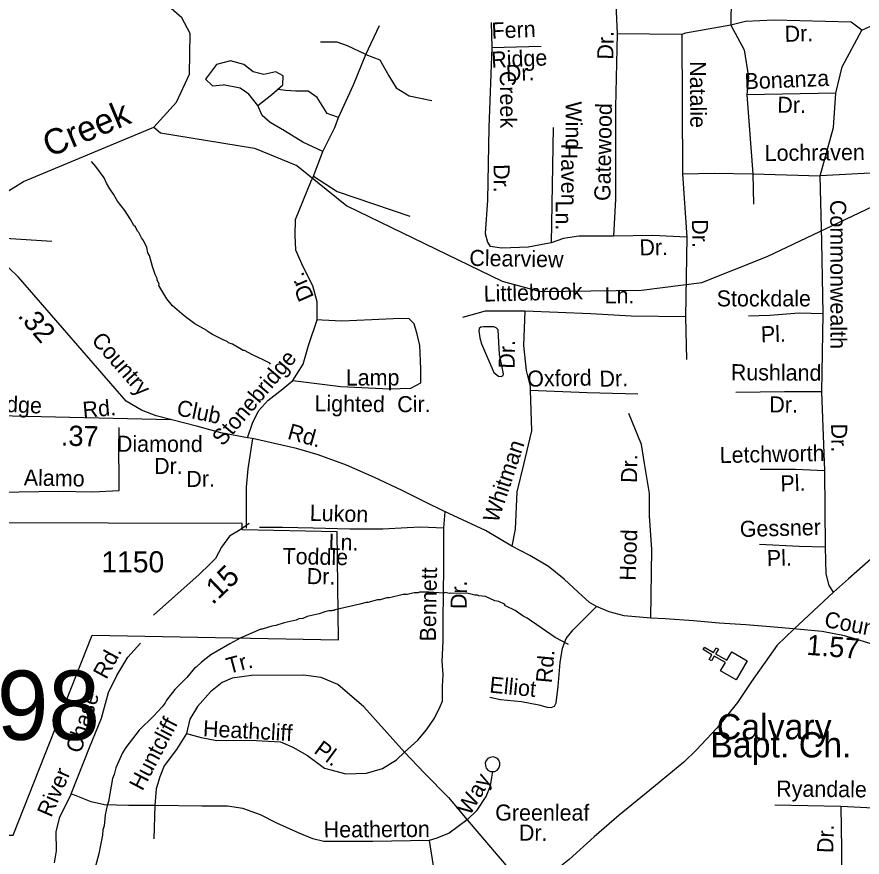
# Model space of a CAD drawing. Extents: x 1547597 to 1699558, y 810033 to 920809.
# Drawn here: x 1597107 to 1602112, y 851025 to 855999 of the extents above; entities that cross this region are included whole.
import ezdxf

# ---------------------------------------------------------------- set-up
doc = ezdxf.new("R2010")
doc.units = 0
for name, color, linetype in [('Exist Boundary Political City Limit New', 7, 'Continuous'), ('Exist Cultural Church CELL', 7, 'Continuous'), ('Exist Cultural Church Label', 7, 'Continuous'), ('Exist Hydrographic Creek Single Shore', 7, 'Continuous'), ('Exist Hydrographic Misc Water Feature', 7, 'Continuous'), ('Exist Road Non-System Type 51', 7, 'Continuous'), ('Exist Road Non-System Type 51 Label', 7, 'Continuous'), ('Exist Road Secondary Mileage Hundredths English Label', 7, 'Continuous'), ('Exist Road Secondary Structure Standard Bridge CELL', 7, 'Continuous'), ('Exist Road Secondary Structure Standard Bridge Number Label', 7, 'Continuous'), ('Exist Road Secondary Type 51 Attributed', 7, 'Continuous'), ('Exist Road Secondary Type 51 Label', 7, 'Continuous'), ('Exist Road Secondary Type 51 Number Label', 7, 'Continuous'), ('Map Preparation Boundary City Limit Buffer Line', 7, 'Continuous'), ('Old_Level_32', 7, 'Continuous')]:
    doc.layers.add(name, color=color, linetype=linetype)

msp = doc.modelspace()

# ---------------------------------------------------------------- linework, layer by layer
at = {"layer": 'Exist Boundary Political City Limit New'}
msp.add_lwpolyline([(1598966.2, 848889), (1598696.7, 848933.6), (1598735.8, 849260.4), (1597051.5, 849266), (1596744.3, 849248.9), (1596741.6, 849203.1), (1596587.6, 849194.5), (1596790.6, 850274.8), (1596971.2, 851155.7), (1597083.9, 851155.7), (1597552.8, 852338.7), (1599010.8, 852311.7), (1599004, 852951.6), (1598440.1, 852963.6), (1598441.2, 853000.9), (1596057.5, 853006.4)], dxfattribs=at)
at = {"layer": 'Exist Cultural Church CELL'}
msp.add_lwpolyline([(1601273.5, 852127.9), (1601302.2, 852177), (1601236.5, 852215.5), (1601220.4, 852187.9), (1601206.6, 852196), (1601222.8, 852223.6), (1601170.9, 852254), (1601179, 852267.9), (1601230.9, 852237.4), (1601247, 852265), (1601260.8, 852257), (1601244.6, 852229.4), (1601310.3, 852190.9), (1601339.6, 852240.5), (1601431.4, 852186.7), (1601365.4, 852074)], close=True, dxfattribs=at)
at = {"layer": 'Exist Hydrographic Creek Single Shore'}
for points in [[(1597916.6, 855346.8), (1598051.6, 855495), (1598128.7, 855660.9), (1598132.7, 855900.5), (1598083.7, 855993.4), (1597959.6, 856104.2), (1597769.6, 856200), (1597613.6, 856400.1), (1597549.6, 856634.5), (1597500.6, 856710.9), (1597454.7, 856961.4), (1597490.7, 857151.1), (1597755.1, 857446.8), (1598364.4, 858096.9), (1598493.9, 858519.8), (1598638.6, 858913.6)], [(1596005.6, 853287.9), (1596117.6, 853594.1), (1596743.8, 854808.1), (1596918.7, 854884.4), (1597145.7, 855024.3), (1597916.6, 855346.8)]]:
    msp.add_lwpolyline(points, dxfattribs=at)
at = {"layer": 'Exist Hydrographic Misc Water Feature'}
for points in [[(1597916.6, 855346.8), (1597957.7, 855313.1), (1598514.6, 855223), (1598763.6, 855119.5), (1599060.6, 854880.4), (1599980.6, 854435), (1600204.6, 854374.6), (1600804.6, 854382.2), (1601163.6, 854427.4), (1601549.7, 854580.4), (1602405.6, 854986.5), (1603296.7, 855565.9), (1603514.7, 855656.7), (1603614.6, 855661.2)], [(1598609.3, 853943), (1598605.4, 853949), (1598565.7, 853969.5), (1598502.2, 853998.5), (1598454.6, 854025.1), (1598446.6, 854025.2), (1598383.1, 854062.1), (1598359.3, 854070.4), (1598351.4, 854078.5), (1598327.5, 854086.9), (1598264, 854119.7), (1598240.1, 854134.1), (1598232.3, 854142.2), (1598160.9, 854183.2), (1598097.6, 854230.1), (1598028.4, 854289), (1597995, 854329.5), (1597948.1, 854410.1), (1597948.2, 854418.1), (1597936.5, 854442.2), (1597936.6, 854450.2), (1597925, 854474.4), (1597909.7, 854522.6), (1597892.6, 854586.9), (1597882.8, 854602.9), (1597875.2, 854635), (1597855.7, 854675.3), (1597844, 854691.5), (1597828.5, 854723.7), (1597820.6, 854731.8), (1597808.9, 854756), (1597799.1, 854764.1), (1597777.6, 854804.4), (1597746.3, 854852.8), (1597703.1, 854909.4), (1597679.6, 854949.7), (1597656, 854982), (1597636.5, 855014.3), (1597623, 855046.5), (1597573.9, 855113.2), (1597547.8, 855142.6)], [(1599847.2, 854098.7), (1599857.4, 854064.7), (1599930.7, 853893.6), (1599959.1, 853871.7), (1599974.8, 853869.7), (1599985.9, 853876.6), (1599988.9, 853887.1), (1599965.1, 854001.7), (1599956.2, 854147), (1599945.2, 854159.4), (1599931.9, 854164.8), (1599869, 854165.5), (1599854.3, 854161.6), (1599845, 854154.7), (1599841.3, 854141.3), (1599847.2, 854098.7)], [(1600373.7, 852284.7), (1600294.3, 852325.8), (1600127.9, 852440.1), (1600104.1, 852452.4), (1600056.7, 852485.1), (1600001, 852513.8), (1599993.2, 852522), (1599961.4, 852538.4), (1599937.4, 852542.7), (1599881.9, 852567.5), (1599842, 852572.1), (1599834, 852576.2), (1599818, 852576.4), (1599778.1, 852584.9), (1599674.3, 852588.4), (1599666.3, 852586.5), (1599642.3, 852590.8), (1599634.3, 852586.9), (1599546.4, 852594.2), (1599490.4, 852593), (1599482.3, 852589.1), (1599458.4, 852589.4), (1599418.2, 852580), (1599394.3, 852580.3), (1599314.1, 852559.5), (1599298.1, 852559.7), (1599257.9, 852548.2), (1599242, 852548.4), (1599185.8, 852533.2), (1599175.8, 852533.4), (1599137.6, 852521.9), (1598991.3, 852489.9), (1598985.3, 852486), (1598975.2, 852486.1), (1598969.2, 852482.3), (1598953.2, 852482.5), (1598929.2, 852476.8), (1598897, 852465.3), (1598824.8, 852450.3), (1598800.7, 852438.6), (1598776.6, 852434.9), (1598760.5, 852427.2), (1598688.4, 852412.2), (1598640.2, 852396.8), (1598616.2, 852393.2), (1598560, 852374), (1598552, 852374.1), (1598433.4, 852323.7), (1598366.9, 852288.7), (1598256, 852222.2), (1598199.5, 852179.1), (1598169.1, 852149.5), (1598159, 852143.6), (1598112.3, 852088.3), (1598041.4, 852017.3), (1597992.5, 851954), (1597984.3, 851938.1), (1597966.1, 851914.4), (1597915.3, 851859.1), (1597830.2, 851776.3), (1597750.9, 851673.4), (1597732.4, 851641.7), (1597693.2, 851554.2), (1597682.7, 851514.4), (1597672.4, 851490.6), (1597648.5, 851354.9), (1597640.2, 851331), (1597629.5, 851275.2), (1597622.6, 851211.3), (1597616.2, 851187.4), (1597613.9, 851155.5), (1597596.8, 851075.7), (1597594.4, 851051.8), (1597569.3, 850964.1)]]:
    msp.add_lwpolyline(points, dxfattribs=at)
at = {"layer": 'Exist Road Non-System Type 51'}
msp.add_line((1599635.2, 852975.4), (1599641.8, 853069.4), dxfattribs=at)
for points in [[(1601338.2, 856272.2), (1601333.9, 855950.3)], [(1600647.8, 856208.1), (1600660.9, 855899.3)], [(1602110.2, 855920.2), (1602046.7, 855967.7), (1601590.3, 855980.8), (1601420.8, 855972.1), (1601333.9, 855950.3)], [(1599172.4, 855776.7), (1599253, 855948.7)], [(1599914.8, 855966.3), (1599919.1, 855818.4)], [(1601333.9, 855950.3), (1601065.1, 855903.6), (1601043.4, 855894.9)], [(1601333.9, 855950.3), (1601412.9, 855803.6), (1601438.9, 855642.6), (1601429.5, 855537.1)], [(1601956.2, 855547), (1601993.9, 855704.5), (1602110.2, 855920.2), (1602161.5, 855944.2), (1602243.6, 855944.2), (1602298.3, 855886), (1602339.4, 855776.4), (1602336, 855666.8), (1602329.1, 855601.8), (1602342.8, 855512.8), (1602376.9, 855469.4)], [(1600660.9, 855899.3), (1600652.2, 855464.2), (1600652.2, 854920.5), (1600639.3, 854700.6)], [(1601043.4, 855894.9), (1600660.9, 855899.3)], [(1601043.4, 855894.9), (1601047.4, 855070.1)], [(1599172.4, 855776.7), (1599065, 855827.7), (1599003.2, 855849.3), (1598903.8, 855849.3)], [(1599919.1, 855818.4), (1600210.3, 855827.1)], [(1599011.3, 855403), (1599099.9, 855596.6), (1599172.4, 855776.7)], [(1599172.4, 855776.7), (1599255.7, 855744.4), (1599309.4, 855650.3), (1599352.4, 855580.4), (1599430.3, 855532.1), (1599564.6, 855505.2)], [(1599919.1, 855818.4), (1599901.7, 855344.2), (1599893, 854913.6), (1599880, 854717.8), (1599893, 854665.6), (1599909, 854639.7)], [(1598533.2, 855475.6), (1598616.4, 855540.1), (1598680.9, 855596.6), (1598683.6, 855650.3), (1598640.6, 855674.5), (1598568.1, 855658.4), (1598506.3, 855674.5), (1598449.9, 855717.5), (1598372, 855739), (1598288.7, 855717.5), (1598224.3, 855631.5), (1598264.6, 855591.2), (1598329, 855596.6)], [(1598533.2, 855475.6), (1598479.4, 855542.8), (1598428.4, 855577.8), (1598329, 855596.6)], [(1599011.3, 855403), (1598944.1, 855427.2), (1598885, 855521.3), (1598831.3, 855558.9), (1598758.8, 855558.9), (1598699.7, 855564.3), (1598651.3, 855569.7)], [(1601956.2, 855547), (1601429.5, 855537.1)], [(1601429.5, 855537.1), (1601464.7, 855070.1)], [(1601863.8, 855058.6), (1601942.6, 855345), (1601956.2, 855547)], [(1598917.5, 855202.7), (1598799.1, 855257.9), (1598691.6, 855325.1), (1598605.7, 855373.5), (1598560, 855416.5), (1598533.2, 855475.6)], [(1598917.5, 855202.7), (1598990, 855345.1), (1599011.3, 855403)], [(1600282.9, 855344.4), (1600269.8, 854661.5)], [(1598863.7, 855057.5), (1598917.5, 855202.7)], [(1601047.4, 855070.1), (1601238.6, 855074.4), (1601464.7, 855070.1)], [(1602199, 855075.7), (1601863.8, 855058.6)], [(1598885.3, 854206.8), (1598885.2, 854312.9), (1598858.4, 854407), (1598802, 854519.9), (1598759, 854619.4), (1598753.6, 854708.1), (1598756.3, 854799.5), (1598847.6, 855022.6), (1598863.7, 855057.5)], [(1598863.7, 855057.5), (1599003.2, 854964.9), (1599433, 854819.7)], [(1601047.4, 855070.1), (1601074, 854696.3)], [(1601464.7, 855070.1), (1601469, 854891.7)], [(1601464.7, 855070.1), (1601863.8, 855058.6)], [(1601882, 854241.3), (1601873.3, 854670.3), (1601863.8, 855058.6)], [(1600639.3, 854700.6), (1600435, 854700.6), (1600343.7, 854687.6), (1600269.8, 854661.5)], [(1601074, 854696.3), (1600869.7, 854705), (1600639.3, 854700.6)], [(1601074, 854696.3), (1601066.6, 854223.2)], [(1600269.8, 854661.5), (1600135.1, 854635.4), (1599978.6, 854631), (1599909, 854639.7)], [(1600114.7, 854258), (1599880, 854258), (1599745.2, 854218.9)], [(1600114.7, 854258), (1600106, 854054.4), (1600123.4, 853906.5), (1600145.2, 853810.8), (1600145.2, 853789.1)], [(1601066.6, 854223.2), (1600745, 854227.6), (1600505.9, 854240.6), (1600114.7, 854258)], [(1601066.6, 854223.2), (1601071, 853970.9)], [(1601882, 854241.3), (1601738.5, 854245.6), (1601564.7, 854232.6), (1601438.6, 854228.2)], [(1601873.3, 853780.2), (1601882, 854241.3)], [(1598740.3, 853846.6), (1599025, 853811.6), (1599312.4, 853798.2), (1599438.6, 853800.9), (1599497.7, 853833.1), (1599497.7, 853916.4), (1599492.4, 854053.5), (1599476.2, 854120.7), (1599460.1, 854182.6), (1599427.9, 854214.8), (1599333.9, 854212.1), (1599207.6, 854206.8), (1599030.4, 854198.7), (1598914.9, 854204.1), (1598885.3, 854206.8)], [(1598740.3, 853846.6), (1598802.1, 853943.3), (1598834.3, 854053.5), (1598885.3, 854206.8)], [(1598471.7, 853507.9), (1598503.9, 853599.3), (1598538.8, 853669.1), (1598592.6, 853728.3), (1598681.2, 853798.2), (1598740.3, 853846.6)], [(1600145.2, 853789.1), (1600153.9, 853549.8), (1600106, 853349.7), (1600066.9, 853188.7), (1600058.2, 852966.9), (1600037.5, 852866.9)], [(1600145.2, 853789.1), (1600484.2, 853776), (1600784.1, 853767.3)], [(1601873.3, 853780.2), (1601651.6, 853780.2), (1601364.7, 853775.8)], [(1601890.8, 853311.7), (1601873.3, 853780.2)], [(1600860.7, 852440.7), (1600865.9, 852846.3), (1600852.9, 853046.4), (1600852.9, 853176.9), (1600822.5, 853355.2), (1600805.1, 853468.3), (1600731.2, 853651)], [(1597712.1, 853195.5), (1597711.4, 853271.5), (1597710.6, 853437.4), (1597712.9, 853569.4)], [(1598501, 853503.6), (1598474.1, 853323.1), (1598464.4, 853215.8)], [(1601890.8, 853311.7), (1601716.9, 853320.4), (1601508.2, 853320.4)], [(1601895.1, 852859.3), (1601890.8, 853311.7)], [(1602596.4, 853240.2), (1602213.2, 852832.8), (1602031.9, 852671.8), (1601943, 852593.1)], [(1596622.8, 853179.5), (1596724.9, 853179.7), (1596916.6, 853182.2), (1597120.4, 853188.4), (1597352.4, 853192.1), (1597556.1, 853188.4), (1597712.1, 853195.5)], [(1598464.4, 853215.8), (1598464.4, 852971.8)], [(1598542.7, 852979.1), (1598679, 852977.9), (1598860.6, 852974.4), (1599078.2, 852968.4), (1599274.1, 852968.9), (1599417.5, 852976.7), (1599499.6, 852979.9), (1599635.2, 852975.4)], [(1599402.5, 851647.4), (1599480.5, 851718.2), (1599531.6, 851777.9), (1599579.3, 851847.3), (1599612.5, 851916.7), (1599626.7, 851948.6), (1599627, 852034.5), (1599630.5, 852106.3), (1599624.2, 852185.3), (1599631.5, 852302.4), (1599630.3, 852439.1), (1599632.7, 852574.9), (1599634, 852751.2), (1599635.2, 852975.4)], [(1601895.1, 852859.3), (1601738.6, 852863.7), (1601503.9, 852876.7)], [(1601943, 852593.1), (1601916.8, 852632.4), (1601899.4, 852702), (1601895.1, 852859.3)], [(1601943, 852593.1), (1601706.9, 852374)], [(1599906.9, 851971.7), (1599970.6, 851958.6), (1600094.2, 851946.2), (1600197.7, 851926.3), (1600246.8, 851912.7), (1600270, 851910.7), (1600289.6, 851918.5), (1600299.8, 851938.5), (1600311.6, 852036.1), (1600324.3, 852177.9), (1600337.8, 852261.7), (1600358.9, 852319.1), (1600399.8, 852370.5), (1600448.6, 852417.5), (1600538.3, 852509.8)], [(1601706.9, 852374), (1601608, 852279.6), (1601457.3, 852064.2), (1601373.2, 851940.8), (1601251.8, 851788), (1601128.6, 851658.7), (1601056.1, 851588.2), (1600853.8, 851421.5), (1600673.8, 851272.6), (1600525, 851145.3), (1600376.3, 851010.2), (1600267.8, 850924.9)], [(1597427.1, 851399), (1597536.8, 851673.7), (1597607.5, 851846.9), (1597648.9, 852000.6), (1597697.7, 852100.6), (1597763.5, 852208), (1597839.1, 852290.9)], [(1599402.5, 851647.4), (1599161.6, 851915.4), (1599008.1, 852047.1), (1598908.1, 852088.6), (1598803.3, 852103.2), (1598496.1, 852100.8), (1598381.6, 852083.7), (1598323.1, 852059.3), (1598252.4, 852003.2), (1598176.8, 851917.8), (1598130.5, 851842.2), (1598111, 851756.8)], [(1598111, 851756.8), (1598052.5, 851661.7), (1597979.4, 851566.5), (1597952.6, 851500.7), (1597930.6, 851429.9), (1597923.3, 851329.9)], [(1598111, 851756.8), (1598198.8, 851732.4), (1598291.4, 851715.3), (1598388.9, 851717.8), (1598523, 851715.3), (1598666.8, 851708), (1598739.9, 851676.3), (1598827.7, 851627.5), (1598927.6, 851551.9), (1599054.4, 851517.7), (1599176.3, 851522.6), (1599271.3, 851549.4), (1599354.2, 851600.7), (1599402.5, 851647.4)], [(1599402.5, 851647.4), (1599519.5, 851523), (1599662.1, 851378.5), (1599773.1, 851245.5)], [(1599924.6, 851531.6), (1599936.2, 851532.8), (1599950, 851539.9), (1599960.6, 851551.1), (1599967.2, 851569), (1599966.5, 851584), (1599960.2, 851598.8), (1599951.7, 851608.3), (1599938.7, 851615.8), (1599926.1, 851618.7), (1599908.7, 851615.8), (1599895.7, 851608.3), (1599886.3, 851598.1), (1599880.4, 851583.4), (1599880.7, 851568.4), (1599885.2, 851552.7), (1599896, 851540.8), (1599911.6, 851532.5), (1599924.6, 851531.6)], [(1599773.1, 851245.5), (1599831.6, 851304), (1599885.3, 851384.5), (1599912.1, 851448), (1599919.4, 851496.8), (1599924.6, 851531.6)], [(1597427.1, 851399), (1597356.4, 851255), (1597336.9, 851174.5), (1597339.4, 851062.3), (1597327.2, 850991.6)], [(1597923.3, 851329.9), (1597768.4, 851330.7), (1597624.6, 851335.6), (1597546.6, 851352.6), (1597427.1, 851399)], [(1601986.3, 851327.4), (1602332.8, 851309.9), (1602393.8, 851303.3), (1602439.6, 851288.1), (1602513.7, 851272.8), (1602655.3, 851248.8), (1602757.7, 851233.5), (1602818.7, 851222.6), (1602916.8, 851224.8), (1602956, 851224.8), (1602988.7, 851261.9), (1603054, 851329.5), (1603092.5, 851383.8)], [(1597923.3, 851329.9), (1597917.1, 851133.1)], [(1599548.9, 851123.5), (1599214.9, 851118.6), (1599054, 851118.6), (1598924.8, 851118.6), (1598859, 851133.3), (1598778.6, 851167.4), (1598646.9, 851226), (1598549.4, 851274.8), (1598444.6, 851313.8), (1598354.4, 851326), (1598200.9, 851326), (1597923.3, 851329.9)], [(1601594.1, 851333.9), (1601986.3, 851327.4)], [(1601986.3, 851327.4), (1601990.6, 851072.1), (1601990.6, 850906.1)], [(1599773.1, 851245.5), (1599665.9, 851167.4), (1599592.8, 851138.2), (1599548.9, 851123.5)], [(1599773.1, 851245.5), (1600139.5, 850815.8)], [(1599548.9, 851123.5), (1599578.1, 850935.7)]]:
    msp.add_lwpolyline(points, dxfattribs=at)
at = {"layer": 'Exist Road Secondary Structure Standard Bridge CELL'}
msp.add_line((1597039, 854689.6), (1597314.3, 854671.5), dxfattribs=at)
at = {"layer": 'Exist Road Secondary Type 51 Attributed'}
for points in [[(1598015.9, 853615.1), (1597931.9, 853636.9), (1597844.8, 853671.2), (1597754.5, 853724.1), (1597117, 854457.7), (1596942.9, 854624), (1596772.6, 854822.1)], [(1596103.5, 852639.6), (1596169.3, 852683.2), (1596283.5, 852774.6), (1596371.6, 852874.3), (1596431, 853004.5), (1596556.7, 853256.2), (1596616.2, 853394.7), (1596670.6, 853490.5), (1596699.1, 853529.3), (1596739.2, 853565.6), (1596770.3, 853596.7), (1596827.5, 853623.6), (1596994, 853639.4), (1598015.9, 853615.1)], [(1602228.2, 852267.3), (1602069, 852317.6), (1602007.2, 852335.6), (1601875.4, 852360.2), (1601703.3, 852375.8), (1601591.5, 852387), (1601423.9, 852400.4), (1601265.2, 852409.4), (1601113.3, 852425), (1600945.6, 852436.2), (1600860.7, 852440.7), (1600703, 852452.8), (1600613.5, 852476.4), (1600538.3, 852509.8), (1600496.7, 852532.6), (1600430, 852593.8), (1600347.5, 852671.3), (1600254.9, 852744.8), (1600144.2, 852810.9), (1600037.5, 852866.9), (1599880.7, 852959.6), (1599663.7, 853059.6), (1599554, 853113.3), (1599388.3, 853196.3), (1599224.9, 853271.9), (1599059.2, 853345.1), (1598891, 853406.1), (1598761.8, 853445.1), (1598501, 853503.6), (1598471.7, 853507.9), (1598313.7, 853536.2), (1598177.8, 853574.6), (1598015.9, 853615.1)], [(1598481.3, 853000.5), (1598428.7, 852963), (1598366.1, 852926.1), (1598317.8, 852860.7), (1598283.1, 852793.5), (1598251.3, 852761), (1598186.2, 852698.6), (1597915.4, 852458.3)]]:
    msp.add_lwpolyline(points, dxfattribs=at)
at = {"layer": 'Map Preparation Boundary City Limit Buffer Line'}
msp.add_lwpolyline([(1598966.2, 848889), (1598696.7, 848933.6), (1598735.8, 849260.4), (1597051.5, 849266), (1596744.3, 849248.9), (1596741.6, 849203.1), (1596587.6, 849194.5), (1596790.6, 850274.8), (1596971.2, 851155.7), (1597083.9, 851155.7), (1597552.8, 852338.7), (1599010.8, 852311.7), (1599004, 852951.6), (1598440.1, 852963.6), (1598441.2, 853000.9), (1596057.5, 853006.4)], dxfattribs=at)

# ---------------------------------------------------------------- texts
at = {"layer": 'Exist Cultural Church Label'}
for s, p in [('Calvary', (1601251.4, 851722.4)), ('Bapt. Ch.', (1601212.6, 851615.1))]:
    msp.add_text(s, height=150, dxfattribs=at).set_placement(p)
at = {"layer": 'Exist Road Non-System Type 51 Label'}
for s, rotation, p in [('Fern', 2.4294, (1599919.2, 855870.4)), ('Dr.', 1.5744, (1601654.2, 855851.2)), ('Dr.', 89.4154, (1600638.6, 855746.3)), ('Ridge', 2.4294, (1599917.6, 855698.1)), ('Natalie', 270.3683, (1601091.9, 855737)), ('Creek', 270.5596, (1599966.3, 855679.4)), ('Dr.', 2.4294, (1600004.3, 855618.2)), ('Bonanza', 2.3773, (1601417.3, 855570.4)), ('Dr.', 359.5127, (1601609.7, 855432.1)), ('Wind', 270.0169, (1600356.9, 855499.4)), ('Gatewood', 88.9521, (1600620.4, 854908.9)), ('Haven', 270.0169, (1600329.8, 855249.2)), ('Lochraven', 0.5347, (1601535.2, 855146.2)), ('Dr.', 270.5596, (1599929, 855127.5)), ('Ln.', 270.0169, (1600297.6, 854912.1)), ('Commonwealth', 270.1106, (1601922.7, 854915.8)), ('Dr.', 271.2978, (1601103.8, 854800.2)), ('Dr.', 0.8563, (1600793.8, 854587)), ('Clearview', 359.0563, (1599785.3, 854525.6)), ('Dr.', 113.9453, (1598867.8, 854341.9)), ('Littlebrook', 1.4021, (1599871.9, 854313.6)), ('Ln.', 359.5778, (1600587, 854304.1)), ('Stockdale', 0.0048, (1601250.7, 854285.4)), ('Pl.', 1.7337, (1601513.7, 854072.6)), ('Dr.', 89.005, (1600053.6, 853916.4)), ('Stonebridge', 49.7214, (1598325.8, 853453.6)), ('Rushland', 359.6111, (1601334, 853848.8)), ('Lamp', 0.0231, (1599054.2, 853817.2)), ('Oxford', 1.0753, (1600129.6, 853809.8)), ('Dr.', 1.5312, (1600557.8, 853809.2)), ('Lighted', 359.2625, (1598868.5, 853664.6)), ('Cir.', 0.3014, (1599359.1, 853659.1)), ('Dr.', 359.6111, (1601562.1, 853658)), ('Dr.', 270.6188, (1601928.3, 853591.4)), ('Diamond', 359.8157, (1597698.9, 853425)), ('Whitman', 71.459, (1599954.7, 852999)), ('Letchworth', 1.1062, (1601269.1, 853358)), ('Dr.', 0.2889, (1597919.5, 853293.5)), ('Dr.', 88.9289, (1600778.7, 853239.8)), ('Alamo', 358.9496, (1597146.8, 853225.5)), ('Dr.', 0.6539, (1598110.4, 853216.2)), ('Pl.', 2.2528, (1601629.9, 853189.1)), ('Lukon', 358.4169, (1598840, 853016.4)), ('Gessner', 1.4268, (1601388.7, 852920.2)), ('Ln.', 358.4169, (1598951.7, 852844.7)), ('Hood', 88.0425, (1600770.3, 852660.2)), ('Toddle', 358.901, (1598678.9, 852760.8)), ('Pl.', 1.4268, (1601548.8, 852747.4)), ('Dr.', 358.901, (1598822.2, 852641.8)), ('Bennett', 89.0064, (1599587.2, 852301.6)), ('Dr.', 89.0064, (1599769.3, 852493.1)), ('Rd.', 61.5659, (1597636.6, 852072.6)), ('Tr.', 14.9233, (1598361, 852109.1)), ('Rd.', 84.8895, (1600274, 852052.9)), ('Elliot', 354.3118, (1599902.1, 852000)), ('Chase', 72.4853, (1597484.7, 851634.7)), ('Huntcliff', 62.3659, (1597850.3, 851412.4)), ('Heathcliff', 356.9166, (1598206.8, 851740.8)), ('Pl.', 323.6373, (1598859.6, 851645.7)), ('River', 66.6582, (1597309.7, 851255.5)), ('Way', 59.552, (1599788.9, 851266)), ('Ryandale', 359.4549, (1601602.7, 851383.8)), ('Greenleaf', 359.9637, (1599939.1, 851241.4)), ('Heatherton', 0.3089, (1598923.8, 851141.4)), ('Dr.', 359.3225, (1600079.1, 851123.3)), ('Dr.', 88.3651, (1601940, 851048.4))]:
    msp.add_text(s, height=95, rotation=rotation, dxfattribs=at).set_placement(p)
at = {"layer": 'Exist Road Secondary Mileage Hundredths English Label'}
for s, height, rotation, p in [('.32', 120, 310.8176, (1597107, 854228)), ('.37', 120, 358.6377, (1597366.1, 853461.3)), ('.15', 125, 43.7546, (1598265.4, 852514.9)), ('1.57', 120, 355.5195, (1601779.9, 852223.4))]:
    msp.add_text(s, height=height, rotation=rotation, dxfattribs=at).set_placement(p)
at = {"layer": 'Exist Road Secondary Structure Standard Bridge Number Label'}
msp.add_text('98', height=410.1, dxfattribs=at).set_placement((1596988.3, 851719.5))
at = {"layer": 'Exist Road Secondary Type 51 Label'}
for s, rotation, p in [('Country', 311.2256, (1597543, 854081.7)), ('Bridge', 357.516, (1596886.2, 853666.8)), ('Rd.', 5.006, (1597499.7, 853625.1)), ('Club', 348.2303, (1598047.3, 853642)), ('Rd.', 344.1454, (1598703.6, 853502.9)), ('Country', 349.0384, (1601882.8, 852389.3))]:
    msp.add_text(s, height=95, rotation=rotation, dxfattribs=at).set_placement(p)
at = {"layer": 'Exist Road Secondary Type 51 Number Label'}
msp.add_text('1150', height=125, dxfattribs=at).set_placement((1597607.1, 852710.9))
at = {"layer": 'Old_Level_32'}
msp.add_text('Creek', height=150, rotation=22.6956, dxfattribs=at).set_placement((1597298.9, 855166.7))

doc.saveas('drawing.dxf')
